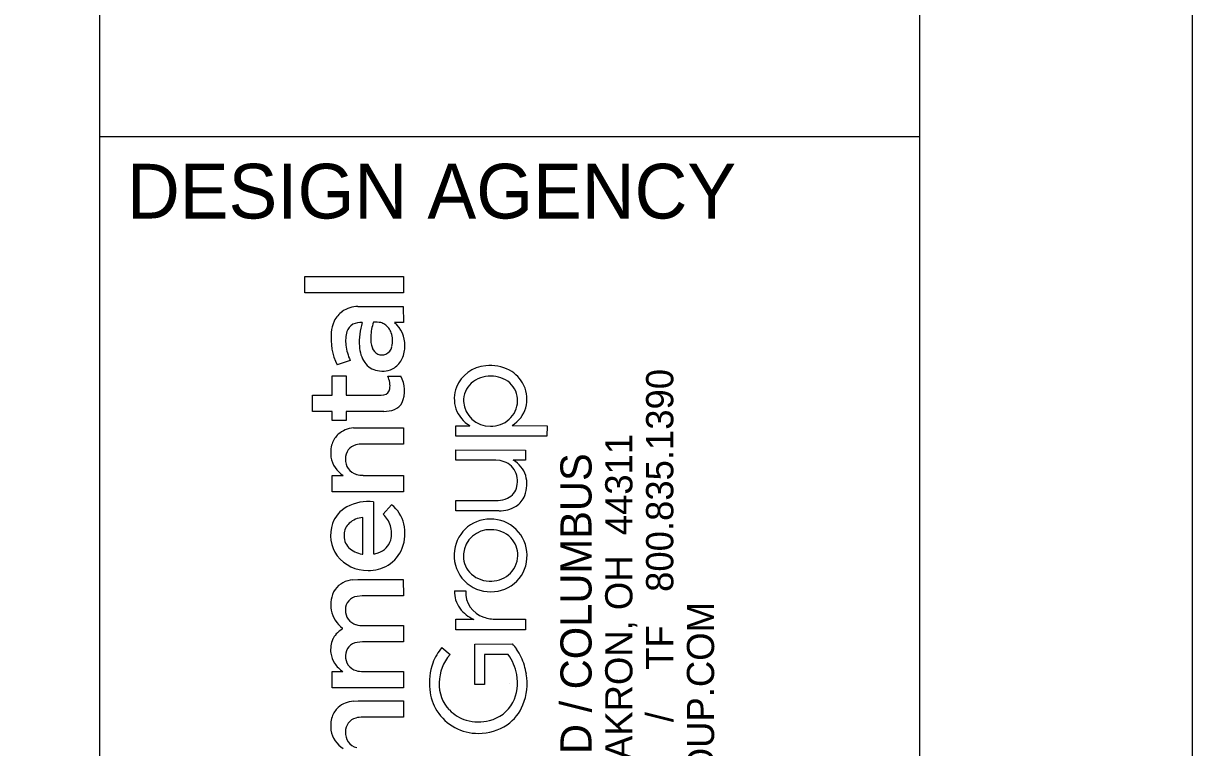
# Model space of a CAD drawing. Extents: x -0.2 to 34, y 0 to 22.
# Drawn here: x 31.86 to 34, y 3.382 to 4.707 of the extents above; entities that cross this region are included whole.
import ezdxf

# ---------------------------------------------------------------- set-up
doc = ezdxf.new("R2010")
doc.units = 0
for name, color, linetype in [('MT_P_Cells', 7, 'Continuous'), ('MT_P_Temp_Road', 7, 'Continuous'), ('SG_P_Poles', 7, 'Continuous')]:
    doc.layers.add(name, color=color, linetype=linetype)

msp = doc.modelspace()

# ---------------------------------------------------------------- linework, layer by layer
at = {"layer": 'MT_P_Cells'}
msp.add_lwpolyline([(0, 0), (34, 0), (34, 22), (0, 22)], close=True, dxfattribs=at)
at = {"layer": 'MT_P_Temp_Road'}
for p, q in [((32, 0.5), (32, 21.5)), ((32, 4.5), (33.5, 4.5))]:
    msp.add_line(p, q, dxfattribs=at)
msp.add_lwpolyline([(1.5, 21.5), (33.5, 21.5), (33.5, 0.5), (1.5, 0.5)], close=True, dxfattribs=at)
at = {"layer": 'SG_P_Poles'}
for p, q in [((32.3756, 4.2141), (32.3756, 4.244)), ((32.3756, 4.244), (32.5557, 4.244)), ((32.5557, 4.244), (32.5557, 4.2141)), ((32.5557, 4.2141), (32.3756, 4.2141)), ((32.4727, 4.189), (32.5555, 4.1892)), ((32.5555, 4.1892), (32.5557, 4.1596)), ((32.5557, 4.1596), (32.5397, 4.1596)), ((32.4582, 4.0904), (32.4343, 4.0823)), ((32.4254, 4.027), (32.4255, 4.0621)), ((32.4255, 4.0621), (32.4511, 4.0621)), ((32.4511, 4.0621), (32.4512, 4.027)), ((32.527, 4.0616), (32.5511, 4.0616)), ((32.3896, 3.9972), (32.3896, 4.027)), ((32.3896, 4.027), (32.4254, 4.027)), ((32.4512, 4.027), (32.515, 4.027)), ((32.515, 4.027), (32.52, 4.0275)), ((32.4254, 3.9972), (32.3896, 3.9972)), ((32.4254, 3.9807), (32.4254, 3.9972)), ((32.4511, 3.9807), (32.4254, 3.9807)), ((32.5197, 3.9972), (32.4511, 3.9972)), ((32.4511, 3.9972), (32.4511, 3.9807)), ((32.4644, 3.9669), (32.4729, 3.9673)), ((32.4729, 3.9673), (32.5557, 3.9673)), ((32.5557, 3.9673), (32.5557, 3.9375)), ((32.6515, 3.9521), (32.6515, 3.9711)), ((32.6515, 3.9711), (32.6771, 3.9711)), ((32.7549, 3.9713), (32.8186, 3.9711)), ((32.8186, 3.9711), (32.8184, 3.9521)), ((32.5557, 3.9375), (32.4814, 3.9375)), ((32.8184, 3.9521), (32.6515, 3.9521)), ((32.6515, 3.908), (32.6515, 3.9267)), ((32.6515, 3.9267), (32.7791, 3.9266)), ((32.7791, 3.9266), (32.7791, 3.908)), ((32.7249, 3.908), (32.6515, 3.908)), ((32.7328, 3.9073), (32.7249, 3.908)), ((32.7791, 3.908), (32.7569, 3.908)), ((32.4254, 3.8503), (32.4254, 3.8802)), ((32.4254, 3.8802), (32.4455, 3.8802)), ((32.4822, 3.8802), (32.5557, 3.8802)), ((32.5557, 3.8802), (32.5557, 3.8504)), ((32.5557, 3.8504), (32.4254, 3.8503)), ((32.5011, 3.8321), (32.5012, 3.7366)), ((32.6515, 3.8344), (32.7291, 3.8345)), ((32.6517, 3.8154), (32.6515, 3.8344)), ((32.5188, 3.8093), (32.5342, 3.8266)), ((32.7307, 3.8154), (32.6517, 3.8154)), ((32.4814, 3.7364), (32.4814, 3.803)), ((32.4802, 3.7363), (32.4814, 3.7364)), ((32.4633, 3.6891), (32.4726, 3.6897)), ((32.4726, 3.6897), (32.5556, 3.6897)), ((32.5556, 3.6897), (32.5557, 3.6598)), ((32.4806, 3.6598), (32.471, 3.6588)), ((32.5557, 3.6598), (32.4806, 3.6598)), ((32.6493, 3.6691), (32.6698, 3.6691)), ((32.6515, 3.598), (32.6515, 3.617)), ((32.6515, 3.617), (32.6848, 3.617)), ((32.726, 3.617), (32.7791, 3.617)), ((32.7791, 3.617), (32.779, 3.598)), ((32.4444, 3.5992), (32.4446, 3.6007)), ((32.4822, 3.6055), (32.5557, 3.6055)), ((32.5557, 3.6055), (32.5557, 3.5757)), ((32.779, 3.598), (32.6515, 3.598)), ((32.4809, 3.5757), (32.4714, 3.5747)), ((32.5557, 3.5757), (32.4809, 3.5757)), ((32.6264, 3.5655), (32.6411, 3.5524)), ((32.6868, 3.5718), (32.7552, 3.5719)), ((32.6868, 3.4978), (32.6868, 3.5718)), ((32.7045, 3.5524), (32.7043, 3.4978)), ((32.7474, 3.5523), (32.7045, 3.5524)), ((32.4254, 3.4915), (32.4254, 3.5214)), ((32.4254, 3.5214), (32.4451, 3.5214)), ((32.4821, 3.5214), (32.5557, 3.5214)), ((32.5557, 3.5214), (32.5557, 3.4916)), ((32.5557, 3.4916), (32.4254, 3.4915)), ((32.7043, 3.4978), (32.6868, 3.4978)), ((32.75, 3.5), (32.75, 3.5)), ((32.4644, 3.4674), (32.4729, 3.4678)), ((32.4729, 3.4678), (32.5557, 3.4678)), ((32.5557, 3.4678), (32.5557, 3.438)), ((32.5557, 3.438), (32.4814, 3.438))]:
    msp.add_line(p, q, dxfattribs=at)
msp.add_lwpolyline([(32.3756, 4.2141), (32.3756, 4.244), (32.5557, 4.244), (32.5557, 4.2141)], close=True, dxfattribs=at)
for points in [[(32.4727, 4.189), (32.5555, 4.1892), (32.5557, 4.1596)], [(32.5557, 4.1596), (32.5397, 4.1596)], [(32.4582, 4.0904), (32.4343, 4.0823)], [(32.5197, 3.9972), (32.4511, 3.9972), (32.4511, 3.9807), (32.4254, 3.9807), (32.4254, 3.9972), (32.3896, 3.9972), (32.3896, 4.027), (32.4254, 4.027), (32.4255, 4.0621), (32.4511, 4.0621), (32.4512, 4.027), (32.515, 4.027), (32.52, 4.0275)], [(32.527, 4.0616), (32.5511, 4.0616)], [(32.4644, 3.9669), (32.4729, 3.9673), (32.5557, 3.9673), (32.5557, 3.9375), (32.4814, 3.9375)], [(32.7549, 3.9713), (32.8186, 3.9711), (32.8184, 3.9521), (32.6515, 3.9521)], [(32.6515, 3.9521), (32.6515, 3.9711), (32.6771, 3.9711)], [(32.7328, 3.9073), (32.7249, 3.908), (32.6515, 3.908), (32.6515, 3.9267), (32.7791, 3.9266), (32.7791, 3.908), (32.7569, 3.908)], [(32.4254, 3.8503), (32.4254, 3.8802), (32.4455, 3.8802)], [(32.4822, 3.8802), (32.5557, 3.8802), (32.5557, 3.8504), (32.4254, 3.8503)], [(32.5011, 3.8321), (32.5012, 3.7366)], [(32.7307, 3.8154), (32.6517, 3.8154), (32.6515, 3.8344), (32.7291, 3.8345)], [(32.5188, 3.8093), (32.5342, 3.8266)], [(32.4802, 3.7363), (32.4814, 3.7364), (32.4814, 3.803)], [(32.4633, 3.6891), (32.4726, 3.6897), (32.5556, 3.6897), (32.5557, 3.6598), (32.4806, 3.6598), (32.471, 3.6588)], [(32.6493, 3.6691), (32.6698, 3.6691)], [(32.6515, 3.598), (32.6515, 3.617), (32.6848, 3.617)], [(32.726, 3.617), (32.7791, 3.617), (32.779, 3.598), (32.6515, 3.598)], [(32.4444, 3.5992), (32.4446, 3.6007)], [(32.4822, 3.6055), (32.5557, 3.6055), (32.5557, 3.5757), (32.4809, 3.5757), (32.4714, 3.5747)], [(32.6264, 3.5655), (32.6411, 3.5524)], [(32.7474, 3.5523), (32.7045, 3.5524), (32.7043, 3.4978), (32.6868, 3.4978), (32.6868, 3.5718), (32.7552, 3.5719)], [(32.4254, 3.4915), (32.4254, 3.5214), (32.4451, 3.5214)], [(32.4821, 3.5214), (32.5557, 3.5214), (32.5557, 3.4916), (32.4254, 3.4915)], [(32.4644, 3.4674), (32.4729, 3.4678), (32.5557, 3.4678), (32.5557, 3.438), (32.4814, 3.438)]]:
    msp.add_lwpolyline(points, dxfattribs=at)
for centre, radius, start, end in [((32.4685, 4.1447), 0.043, 124.537, 155.6594), ((32.4685, 4.1447), 0.043, 124.537, 155.6594), ((32.4745, 4.1326), 0.0565, 91.8942, 122.6317), ((32.4745, 4.1326), 0.0565, 91.8942, 122.6317), ((32.4882, 4.1361), 0.0646, 155.9764, 175.3149), ((32.4882, 4.1361), 0.0646, 155.9764, 175.3149), ((32.4753, 4.1356), 0.024, 119.4252, 161.6629), ((32.4753, 4.1356), 0.024, 119.4252, 161.6629), ((32.4779, 4.1278), 0.0321, 85.3802, 116.6222), ((32.4779, 4.1278), 0.0321, 85.3802, 116.6222), ((32.5879, 4.1251), 0.1129, 162.0821, 184.5285), ((32.5879, 4.1251), 0.1129, 162.0821, 184.5285), ((32.5801, 4.1313), 0.0841, 159.8366, 178.0362), ((32.5801, 4.1313), 0.0841, 159.8366, 178.0362), ((32.5051, 4.1074), 0.053, 79.6696, 94.2322), ((32.5051, 4.1074), 0.053, 79.6696, 94.2322), ((32.5089, 4.1364), 0.0238, 56.8913, 76.2149), ((32.5089, 4.1364), 0.0238, 56.8913, 76.2149), ((32.5052, 4.1318), 0.0297, 17.5984, 55.7282), ((32.5052, 4.1318), 0.0297, 17.5984, 55.7282), ((32.5055, 4.1191), 0.0529, 358.0746, 49.762), ((32.5055, 4.1191), 0.0529, 358.0746, 49.762), ((32.5364, 4.1308), 0.113, 174.6101, 205.3899), ((32.5364, 4.1308), 0.113, 174.6101, 205.3899), ((32.5076, 4.1265), 0.0576, 163.1369, 188.1675), ((32.5076, 4.1265), 0.0576, 163.1369, 188.1675), ((32.5466, 4.1303), 0.0506, 175.5903, 199.8857), ((32.5466, 4.1303), 0.0506, 175.5903, 199.8857), ((32.4916, 4.1264), 0.0443, 345.9408, 18.9919), ((32.4916, 4.1264), 0.0443, 345.9408, 18.9919), ((32.5473, 4.1297), 0.0973, 186.7598, 203.7981), ((32.5473, 4.1297), 0.0973, 186.7598, 203.7981), ((32.5328, 4.1187), 0.0575, 182.5676, 213.7144), ((32.5328, 4.1187), 0.0575, 182.5676, 213.7144), ((32.5164, 4.1189), 0.0184, 198.2844, 293.3081), ((32.5164, 4.1189), 0.0184, 198.2844, 293.3081), ((32.5152, 4.1199), 0.0199, 295.2883, 347.4639), ((32.5152, 4.1199), 0.0199, 295.2883, 347.4639), ((32.5019, 4.1168), 0.0566, 336.016, 0.5951), ((32.5019, 4.1168), 0.0566, 336.016, 0.5951), ((32.5149, 4.1078), 0.0366, 215.0668, 259.8133), ((32.5149, 4.1078), 0.0366, 215.0668, 259.8133), ((32.5175, 4.1097), 0.0394, 303.4436, 336.18), ((32.5175, 4.1097), 0.0394, 303.4436, 336.18), ((32.5175, 4.1131), 0.0423, 257.5256, 300.882), ((32.5175, 4.1131), 0.0423, 257.5256, 300.882), ((32.7108, 4.0182), 0.0624, 93.9866, 158.3119), ((32.7108, 4.0182), 0.0624, 93.9866, 158.3119), ((32.7156, 4.0065), 0.0746, 62.6889, 97.0135), ((32.7156, 4.0065), 0.0746, 62.6889, 97.0135), ((32.7212, 4.0191), 0.0608, 25.0657, 61.9602), ((32.7212, 4.0191), 0.0608, 25.0657, 61.9602), ((32.4863, 4.042), 0.0452, 10.1545, 25.723), ((32.4863, 4.042), 0.0452, 10.1545, 25.723), ((32.4957, 4.0436), 0.0356, 351.914, 10.2059), ((32.4957, 4.0436), 0.0356, 351.914, 10.2059), ((32.503, 4.0351), 0.0549, 336.589, 28.8991), ((32.503, 4.0351), 0.0549, 336.589, 28.8991), ((32.7092, 4.0167), 0.0434, 132.3289, 182.0949), ((32.7092, 4.0167), 0.0434, 132.3289, 182.0949), ((32.7138, 4.0102), 0.0513, 87.8965, 131.1812), ((32.7138, 4.0102), 0.0513, 87.8965, 131.1812), ((32.7175, 4.0102), 0.0513, 49.9089, 92.0363), ((32.7175, 4.0102), 0.0513, 49.9089, 92.0363), ((32.7215, 4.0173), 0.0433, 358.0487, 47.9447), ((32.7215, 4.0173), 0.0433, 358.0487, 47.9447), ((32.7245, 4.02), 0.0574, 301.9776, 25.6418), ((32.7245, 4.02), 0.0574, 301.9776, 25.6418), ((32.5184, 4.04), 0.0126, 277.6142, 353.7918), ((32.5184, 4.04), 0.0126, 277.6142, 353.7918), ((32.707, 4.0202), 0.0581, 158.656, 198.171), ((32.707, 4.0202), 0.0581, 158.656, 198.171), ((32.5291, 4.0261), 0.0275, 292.6889, 332.0598), ((32.5291, 4.0261), 0.0275, 292.6889, 332.0598), ((32.7103, 4.0243), 0.0627, 200.8399, 238.0162), ((32.7103, 4.0243), 0.0627, 200.8399, 238.0162), ((32.7135, 4.0181), 0.0478, 183.5974, 271.7045), ((32.7135, 4.0181), 0.0478, 183.5974, 271.7045), ((32.7172, 4.018), 0.0477, 267.3149, 357.4019), ((32.7172, 4.018), 0.0477, 267.3149, 357.4019), ((32.5209, 4.0486), 0.0514, 268.6727, 291.5235), ((32.5209, 4.0486), 0.0514, 268.6727, 291.5235), ((32.4687, 3.9172), 0.0499, 94.9706, 130.2248), ((32.4687, 3.9172), 0.0499, 94.9706, 130.2248), ((32.4787, 3.9211), 0.056, 162.274, 187.7917), ((32.4787, 3.9211), 0.056, 162.274, 187.7917), ((32.4635, 3.9255), 0.0402, 132.2238, 161.6823), ((32.4635, 3.9255), 0.0402, 132.2238, 161.6823), ((32.4811, 3.8915), 0.046, 89.6051, 105.3303), ((32.4811, 3.8915), 0.046, 89.6051, 105.3303), ((32.4748, 3.9116), 0.025, 103.6868, 182.214), ((32.4748, 3.9116), 0.025, 103.6868, 182.214), ((32.4703, 3.9209), 0.0476, 188.9646, 238.6987), ((32.4703, 3.9209), 0.0476, 188.9646, 238.6987), ((32.4774, 3.9085), 0.0276, 175.5844, 255.1382), ((32.4774, 3.9085), 0.0276, 175.5844, 255.1382), ((32.7271, 3.87), 0.0377, 33.5008, 81.3295), ((32.7271, 3.87), 0.0377, 33.5008, 81.3295), ((32.7324, 3.8648), 0.0496, 17.6221, 60.3897), ((32.7324, 3.8648), 0.0496, 17.6221, 60.3897), ((32.4818, 3.9224), 0.0421, 254.0891, 270.5284), ((32.4818, 3.9224), 0.0421, 254.0891, 270.5284), ((32.7241, 3.8695), 0.0405, 346.5618, 31.7539), ((32.7241, 3.8695), 0.0405, 346.5618, 31.7539), ((32.7234, 3.8641), 0.0584, 339.162, 15.6148), ((32.7234, 3.8641), 0.0584, 339.162, 15.6148), ((32.7337, 3.8662), 0.0304, 294.6321, 348.4863), ((32.7337, 3.8662), 0.0304, 294.6321, 348.4863), ((32.4918, 3.7487), 0.0839, 83.6212, 118.2845), ((32.4918, 3.7487), 0.0839, 83.6212, 118.2845), ((32.7275, 3.8808), 0.0463, 271.952, 294.0894), ((32.7275, 3.8808), 0.0463, 271.952, 294.0894), ((32.739, 3.859), 0.042, 303.1039, 338.1561), ((32.739, 3.859), 0.042, 303.1039, 338.1561), ((32.4789, 3.7737), 0.0558, 118.8294, 160.6224), ((32.4789, 3.7737), 0.0558, 118.8294, 160.6224), ((32.4803, 3.7702), 0.0549, 19.0387, 45.4432), ((32.4803, 3.7702), 0.0549, 19.0387, 45.4432), ((32.494, 3.7763), 0.0644, 13.5328, 51.3627), ((32.494, 3.7763), 0.0644, 13.5328, 51.3627), ((32.7321, 3.8726), 0.0571, 268.627, 301.4778), ((32.7321, 3.8726), 0.0571, 268.627, 301.4778), ((32.487, 3.7707), 0.0644, 160.5214, 215.7815), ((32.487, 3.7707), 0.0644, 160.5214, 215.7815), ((32.477, 3.7709), 0.0298, 132.9855, 177.1802), ((32.477, 3.7709), 0.0298, 132.9855, 177.1802), ((32.4844, 3.7607), 0.0424, 94.0131, 130.8806), ((32.4844, 3.7607), 0.0424, 94.0131, 130.8806), ((32.4872, 3.7743), 0.047, 344.6072, 17.0067), ((32.4872, 3.7743), 0.047, 344.6072, 17.0067), ((32.4829, 3.7738), 0.0758, 339.3543, 13.3771), ((32.4829, 3.7738), 0.0758, 339.3543, 13.3771), ((32.7143, 3.7348), 0.0655, 89.4821, 178.7775), ((32.7143, 3.7348), 0.0655, 89.4821, 178.7775), ((32.7158, 3.7341), 0.0662, 0.4227, 90.7613), ((32.7158, 3.7341), 0.0662, 0.4227, 90.7613), ((32.4782, 3.7697), 0.0311, 175.0014, 223.2876), ((32.4782, 3.7697), 0.0311, 175.0014, 223.2876), ((32.714, 3.7324), 0.0485, 87.6883, 175.017), ((32.714, 3.7324), 0.0485, 87.6883, 175.017), ((32.7166, 3.7304), 0.0505, 44.912, 90.7591), ((32.7166, 3.7304), 0.0505, 44.912, 90.7591), ((32.7196, 3.7345), 0.0455, 358.3228, 43.8349), ((32.7196, 3.7345), 0.0455, 358.3228, 43.8349), ((32.4855, 3.7783), 0.0423, 225.0645, 262.797), ((32.4855, 3.7783), 0.0423, 225.0645, 262.797), ((32.499, 3.7718), 0.035, 288.0108, 343.5536), ((32.499, 3.7718), 0.035, 288.0108, 343.5536), ((32.4955, 3.7698), 0.0626, 300.9439, 338.7322), ((32.4955, 3.7698), 0.0626, 300.9439, 338.7322), ((32.4891, 3.7752), 0.0687, 217.7434, 271.6561), ((32.4891, 3.7752), 0.0687, 217.7434, 271.6561), ((32.5013, 3.7568), 0.0202, 269.7004, 294.8729), ((32.5013, 3.7568), 0.0202, 269.7004, 294.8729), ((32.7148, 3.7334), 0.0661, 177.5373, 270.9452), ((32.7148, 3.7334), 0.0661, 177.5373, 270.9452), ((32.7108, 3.7331), 0.0453, 175.5147, 221.4205), ((32.7108, 3.7331), 0.0453, 175.5147, 221.4205), ((32.7167, 3.7327), 0.0654, 269.3083, 1.6791), ((32.7167, 3.7327), 0.0654, 269.3083, 1.6791), ((32.7193, 3.7337), 0.0457, 308.9038, 359.3095), ((32.7193, 3.7337), 0.0457, 308.9038, 359.3095), ((32.492, 3.777), 0.0706, 269.2053, 300.3357), ((32.492, 3.777), 0.0706, 269.2053, 300.3357), ((32.714, 3.7373), 0.0505, 222.6626, 268.3733), ((32.714, 3.7373), 0.0505, 222.6626, 268.3733), ((32.4664, 3.644), 0.0452, 93.9112, 142.3072), ((32.4664, 3.644), 0.0452, 93.9112, 142.3072), ((32.7157, 3.7386), 0.0518, 266.5531, 308.6725), ((32.7157, 3.7386), 0.0518, 266.5531, 308.6725), ((32.4759, 3.6437), 0.0532, 148.2879, 233.9556), ((32.4759, 3.6437), 0.0532, 148.2879, 233.9556), ((32.4738, 3.635), 0.024, 96.7576, 181.6251), ((32.4738, 3.635), 0.024, 96.7576, 181.6251), ((32.6988, 3.6666), 0.0495, 177.1621, 216.2802), ((32.6988, 3.6666), 0.0495, 177.1621, 216.2802), ((32.7173, 3.6664), 0.0476, 176.7699, 252.1504), ((32.7173, 3.6664), 0.0476, 176.7699, 252.1504), ((32.4758, 3.6324), 0.026, 175.8157, 256.1672), ((32.4758, 3.6324), 0.026, 175.8157, 256.1672), ((32.7098, 3.6755), 0.0637, 216.9153, 246.8862), ((32.7098, 3.6755), 0.0637, 216.9153, 246.8862), ((32.7269, 3.6917), 0.0747, 251.1388, 269.3469), ((32.7269, 3.6917), 0.0747, 251.1388, 269.3469), ((32.4638, 3.5627), 0.0414, 117.9163, 139.243), ((32.4638, 3.5627), 0.0414, 117.9163, 139.243), ((32.4817, 3.6505), 0.045, 254.3463, 270.6103), ((32.4817, 3.6505), 0.045, 254.3463, 270.6103), ((32.4714, 3.5612), 0.0488, 156.0638, 187.3493), ((32.4714, 3.5612), 0.0488, 156.0638, 187.3493), ((32.4619, 3.5645), 0.0387, 139.5245, 154.847), ((32.4619, 3.5645), 0.0387, 139.5245, 154.847), ((32.4742, 3.5506), 0.0243, 96.5532, 179.949), ((32.4742, 3.5506), 0.0243, 96.5532, 179.949), ((32.4646, 3.5597), 0.0418, 186.5579, 213.3885), ((32.4646, 3.5597), 0.0418, 186.5579, 213.3885), ((32.7016, 3.5019), 0.0986, 139.7948, 159.137), ((32.7016, 3.5019), 0.0986, 139.7948, 159.137), ((32.699, 3.5008), 0.0775, 138.258, 179.7006), ((32.699, 3.5008), 0.0775, 138.258, 179.7006), ((32.6789, 3.501), 0.0856, 10.0751, 36.8319), ((32.6789, 3.501), 0.0856, 10.0751, 36.8319), ((32.725, 3.5394), 0.0444, 30.9891, 47.161), ((32.725, 3.5394), 0.0444, 30.9891, 47.161), ((32.6709, 3.5002), 0.1111, 25.3031, 33.9618), ((32.6709, 3.5002), 0.1111, 25.3031, 33.9618), ((32.4789, 3.5708), 0.0598, 214.7043, 235.6872), ((32.4789, 3.5708), 0.0598, 214.7043, 235.6872), ((32.4761, 3.5486), 0.0263, 175.722, 255.7863), ((32.4761, 3.5486), 0.0263, 175.722, 255.7863), ((32.7187, 3.4997), 0.1154, 161.1438, 185.6281), ((32.7187, 3.4997), 0.1154, 161.1438, 185.6281), ((32.6704, 3.4999), 0.1117, 8.8034, 25.3348), ((32.6704, 3.4999), 0.1117, 8.8034, 25.3348), ((32.4819, 3.5652), 0.0438, 253.6672, 270.1498), ((32.4819, 3.5652), 0.0438, 253.6672, 270.1498), ((32.6842, 3.5006), 0.0804, 333.4669, 11.0367), ((32.6842, 3.5006), 0.0804, 333.4669, 11.0367), ((32.6756, 3.4998), 0.1065, 338.2887, 9.2855), ((32.6756, 3.4998), 0.1065, 338.2887, 9.2855), ((32.6934, 3.497), 0.0899, 185.5077, 212.0129), ((32.6934, 3.497), 0.0899, 185.5077, 212.0129), ((32.6881, 3.4973), 0.0668, 176.6658, 223.6912), ((32.6881, 3.4973), 0.0668, 176.6658, 223.6912), ((32.4687, 3.4177), 0.0499, 94.9706, 130.2248), ((32.4687, 3.4177), 0.0499, 94.9706, 130.2248), ((32.4635, 3.426), 0.0402, 132.2238, 161.6823), ((32.4635, 3.426), 0.0402, 132.2238, 161.6823), ((32.6921, 3.4975), 0.0891, 212.7022, 270.714), ((32.6921, 3.4975), 0.0891, 212.7022, 270.714), ((32.6905, 3.5001), 0.0704, 224.0215, 253.88), ((32.6905, 3.5001), 0.0704, 224.0215, 253.88), ((32.6987, 3.4955), 0.0652, 282.8815, 331.8147), ((32.6987, 3.4955), 0.0652, 282.8815, 331.8147), ((32.6984, 3.4917), 0.0824, 305.0306, 337.6757), ((32.6984, 3.4917), 0.0824, 305.0306, 337.6757), ((32.4787, 3.4216), 0.056, 162.274, 187.7917), ((32.4787, 3.4216), 0.056, 162.274, 187.7917), ((32.4748, 3.4121), 0.025, 103.6868, 182.214), ((32.4748, 3.4121), 0.025, 103.6868, 182.214), ((32.4811, 3.392), 0.046, 89.6051, 105.3303), ((32.4811, 3.392), 0.046, 89.6051, 105.3303), ((32.6932, 3.5125), 0.0831, 254.4535, 283.9512), ((32.6932, 3.5125), 0.0831, 254.4535, 283.9512), ((32.6943, 3.4998), 0.0914, 269.3273, 304.1963), ((32.6943, 3.4998), 0.0914, 269.3273, 304.1963), ((32.4703, 3.4214), 0.0476, 188.9646, 238.6987), ((32.4703, 3.4214), 0.0476, 188.9646, 238.6987), ((32.4774, 3.409), 0.0276, 175.5844, 255.1382), ((32.4774, 3.409), 0.0276, 175.5844, 255.1382)]:
    msp.add_arc(centre, radius, start, end, dxfattribs=at)

# ---------------------------------------------------------------- texts
msp.add_text('DESIGN AGENCY', height=0.1, dxfattribs=at).set_placement((32.05, 4.35))
for s, height, p in [('800.835.1390', 0.049846, (33.0497, 3.6671)), ('450 GRANT ST., AKRON, OH  44311', 0.049846, (32.9749, 2.8374)), ('AKRON / CLEVELAND / COLUMBUS', 0.056969, (32.9001, 2.638)), ('ENVDESIGNGROUP.COM', 0.049846, (33.1244, 2.8374)), ('TF', 0.04985, (33.0497, 3.5246)), ('/  ', 0.04985, (33.0497, 3.4288))]:
    msp.add_text(s, height=height, rotation=90, dxfattribs=at).set_placement(p)

doc.saveas('drawing.dxf')
